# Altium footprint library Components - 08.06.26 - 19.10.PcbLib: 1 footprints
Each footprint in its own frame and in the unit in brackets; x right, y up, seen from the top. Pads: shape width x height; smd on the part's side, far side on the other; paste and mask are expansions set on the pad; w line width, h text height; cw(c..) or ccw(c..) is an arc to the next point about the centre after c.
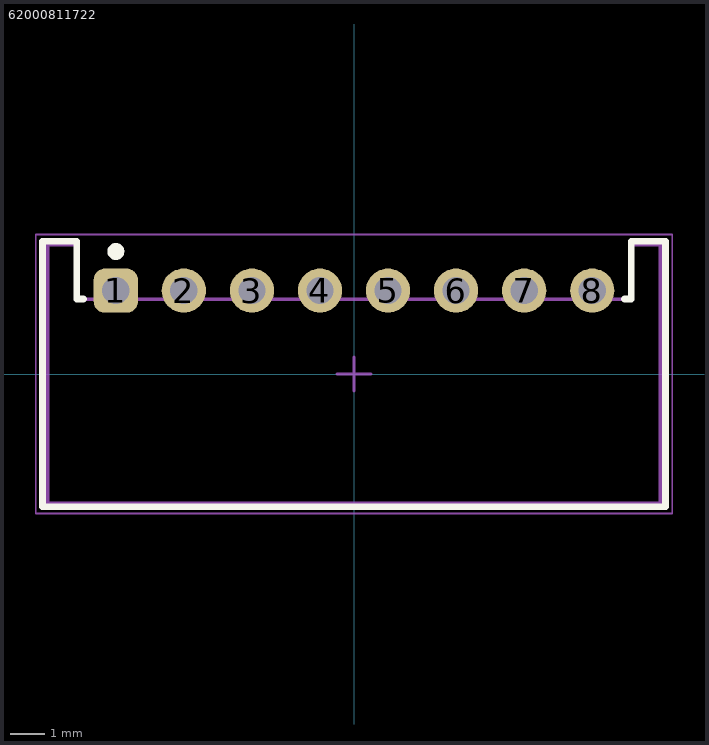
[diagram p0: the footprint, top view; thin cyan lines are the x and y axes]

## 62000811722 [mm] "2.00mm Male Horizontal Shrouded Header, 8p"
height 4.5
pads (8):
  rrect50% 1.3x1.3 hole 0.8: 1(-7,2.45)
  round 1.3 hole 0.8: 2(-5,2.45) 3(-3,2.45) 4(-1,2.45) 5(1,2.45) 6(3,2.45) 7(5,2.45) 8(7,2.45)
Top Overlay:
  circle w0.25: c-7,3.6 r0.125
  lines w0.2: -7.95,2.2 -8.15,2.2 -8.15,3.9 -9.15,3.9 -9.15,-3.9 9.15,-3.9 9.15,3.9 8.15,3.9 8.15,2.2 7.95,2.2
Top Assembly:
  lines w0.1: -9,-3.8 -9,3.8 -8.15,3.8 -8.15,2.2 8.15,2.2 8.15,3.8 9,3.8 9,-3.8 -9,-3.8
Top Designator:
  text ".Designator" at -3.647,-0.357 h1
Top Courtyard:
  lines w0.05: -9.35,-4.1 9.35,-4.1 9.35,4.1 -9.35,4.1 -9.35,-4.1
Top Component Center:
  lines w0.1: -0.5,0 0.5,0 ; 0,-0.5 0,0.5
3D body "62000811722.stp": height 4.83, standoff -3.27, extent -9,-3.8 9,3.8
